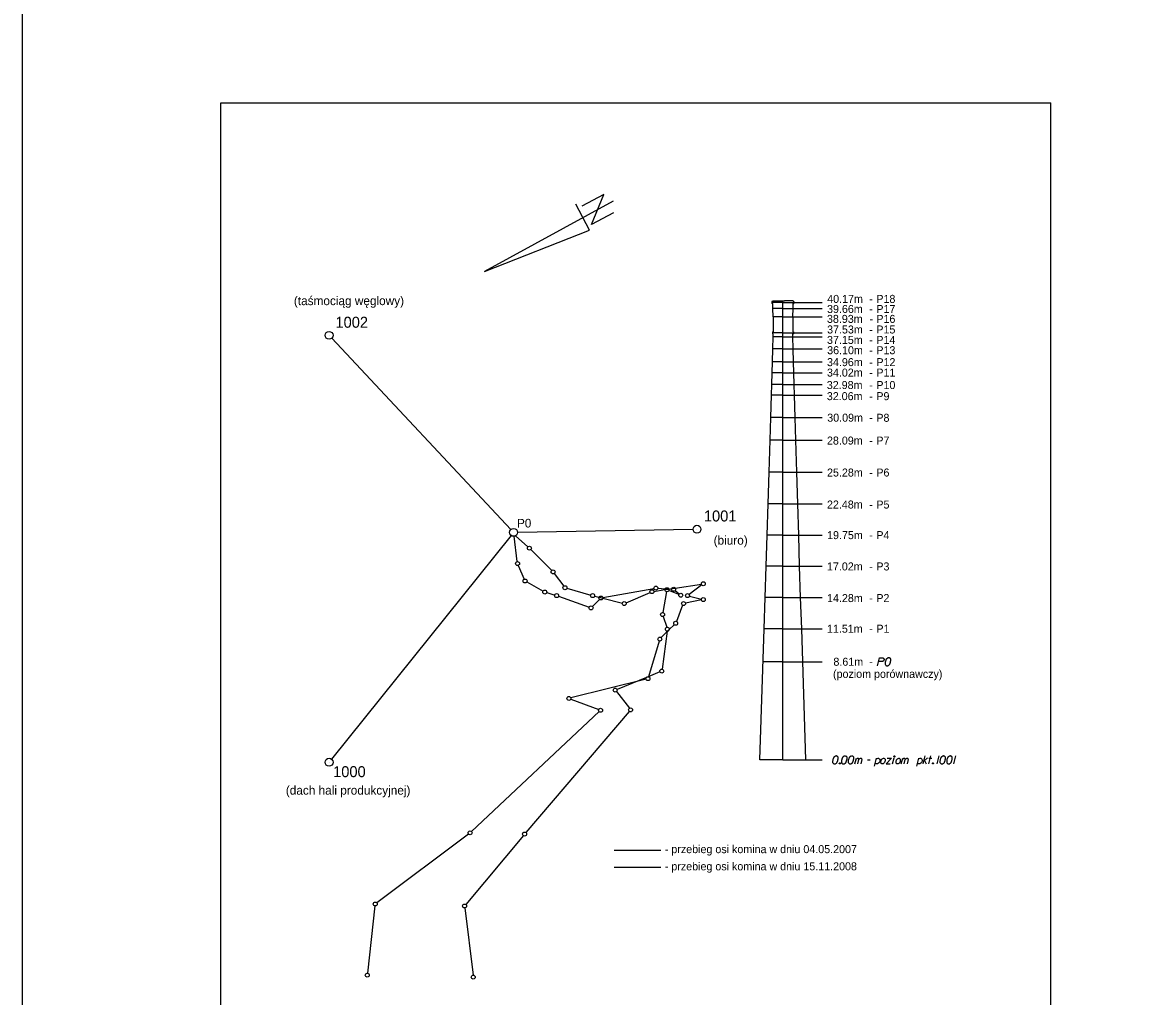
# Model space of a CAD drawing. Extents: x 138 to 6653, y -177 to 1520.
# Drawn here: x 287.42 to 316.02, y -56.31 to -31.68 of the extents above; entities that cross this region are included whole.
import ezdxf

# ---------------------------------------------------------------- set-up
doc = ezdxf.new("R2010")
doc.units = 0
for name, color, linetype in [('15 listopad 2008', 7, 'Continuous'), ('Opisy', 7, 'Continuous'), ('Ramka do drukowania', 7, 'Continuous'), ('Standart wykresów', 7, 'Continuous'), ('Wykresy 15 listopad 2008', 7, 'Continuous'), ('Wykresy 4 maj 2008', 7, 'Continuous')]:
    doc.layers.add(name, color=color, linetype=linetype)

msp = doc.modelspace()

# ---------------------------------------------------------------- linework, layer by layer
at = {"layer": '15 listopad 2008'}
for p, q in [((302.385, -52.613), (303.566, -52.613)), ((302.385, -53.045), (303.566, -53.045))]:
    msp.add_line(p, q, dxfattribs=at)
msp.add_lwpolyline([(287.418, 38.661), (413.872, 38.661), (413.872, -75.347), (287.418, -75.347)], close=True, dxfattribs=at)
at = {"layer": 'Opisy'}
for p, q in [((306.373, -38.741), (306.373, -38.765)), ((306.394, -38.741), (306.373, -38.741)), ((306.652, -38.765), (306.373, -38.765)), ((306.373, -38.765), (306.373, -38.79)), ((306.394, -38.79), (306.373, -38.79)), ((306.394, -38.717), (306.394, -38.741)), ((306.394, -38.717), (306.692, -38.717)), ((306.394, -38.913), (306.394, -38.79)), ((306.652, -50.331), (306.652, -38.717)), ((306.652, -38.765), (307.641, -38.765)), ((306.91, -38.717), (306.692, -38.717)), ((306.91, -38.717), (306.91, -38.741)), ((306.91, -38.741), (306.931, -38.741)), ((306.91, -38.79), (306.931, -38.79)), ((306.91, -38.913), (306.91, -38.79)), ((306.931, -38.741), (306.931, -38.765)), ((306.931, -38.765), (306.931, -38.79)), ((306.652, -38.913), (306.394, -38.913)), ((306.403, -39.123), (306.394, -38.913)), ((306.652, -39.123), (306.403, -39.123)), ((306.403, -39.123), (306.403, -39.501)), ((306.652, -38.913), (307.641, -38.913)), ((306.652, -39.123), (307.641, -39.123)), ((306.901, -39.123), (306.91, -38.913)), ((306.901, -39.123), (306.901, -39.501)), ((306.386, -39.501), (306.386, -39.527)), ((306.386, -39.501), (306.403, -39.501)), ((306.652, -39.527), (306.386, -39.527)), ((306.386, -39.527), (306.386, -39.552)), ((306.405, -39.552), (306.386, -39.552)), ((306.394, -39.939), (306.403, -39.635)), ((306.403, -39.635), (306.405, -39.552)), ((306.652, -39.635), (306.403, -39.635)), ((306.652, -39.527), (307.641, -39.527)), ((306.652, -39.635), (307.641, -39.635)), ((306.901, -39.635), (306.899, -39.552)), ((306.899, -39.552), (306.918, -39.552)), ((306.918, -39.501), (306.901, -39.501)), ((306.91, -39.939), (306.901, -39.635)), ((306.918, -39.501), (306.918, -39.527)), ((306.918, -39.527), (306.918, -39.552)), ((306.386, -40.268), (306.394, -39.939)), ((306.652, -39.939), (306.394, -39.939)), ((306.652, -39.939), (307.641, -39.939)), ((306.918, -40.268), (306.91, -39.939)), ((306.377, -40.538), (306.386, -40.268)), ((306.652, -40.268), (306.386, -40.268)), ((306.652, -40.268), (307.641, -40.268)), ((306.927, -40.538), (306.918, -40.268)), ((306.37, -40.837), (306.377, -40.538)), ((306.652, -40.538), (306.377, -40.538)), ((306.652, -40.538), (307.641, -40.538)), ((306.934, -40.837), (306.927, -40.538)), ((306.36, -41.103), (306.37, -40.837)), ((306.652, -40.837), (306.37, -40.837)), ((306.652, -40.837), (307.641, -40.837)), ((306.944, -41.103), (306.934, -40.837)), ((306.344, -41.67), (306.36, -41.103)), ((306.652, -41.103), (306.36, -41.103)), ((306.652, -41.103), (307.641, -41.103)), ((306.96, -41.67), (306.944, -41.103)), ((306.327, -42.244), (306.344, -41.67)), ((306.652, -41.67), (306.344, -41.67)), ((306.652, -41.67), (307.641, -41.67)), ((306.977, -42.244), (306.96, -41.67)), ((306.304, -43.055), (306.327, -42.244)), ((306.652, -42.244), (306.327, -42.244)), ((306.652, -42.244), (307.641, -42.244)), ((307, -43.055), (306.977, -42.244)), ((306.278, -43.859), (306.304, -43.055)), ((306.652, -43.055), (306.304, -43.055)), ((306.652, -43.055), (307.641, -43.055)), ((307.026, -43.859), (307, -43.055)), ((306.253, -44.645), (306.278, -43.859)), ((306.652, -43.859), (306.278, -43.859)), ((306.652, -43.859), (307.641, -43.859)), ((307.051, -44.645), (307.026, -43.859)), ((306.229, -45.431), (306.253, -44.645)), ((306.652, -44.645), (306.253, -44.645)), ((306.652, -44.645), (307.641, -44.645)), ((307.075, -45.431), (307.051, -44.645)), ((306.204, -46.221), (306.229, -45.431)), ((306.652, -45.431), (306.229, -45.431)), ((306.652, -45.431), (307.641, -45.431)), ((307.1, -46.221), (307.075, -45.431)), ((306.178, -47.017), (306.204, -46.221)), ((306.652, -46.221), (306.204, -46.221)), ((306.652, -46.221), (307.641, -46.221)), ((307.126, -47.017), (307.1, -46.221)), ((306.07, -50.331), (306.178, -47.017)), ((306.652, -47.017), (306.178, -47.017)), ((306.652, -47.017), (307.641, -47.017)), ((307.234, -50.331), (307.126, -47.017)), ((306.652, -47.853), (306.151, -47.853)), ((306.652, -47.853), (307.641, -47.853)), ((306.652, -50.331), (306.07, -50.331)), ((306.652, -50.331), (307.641, -50.331))]:
    msp.add_line(p, q, dxfattribs=at)
for points in [[(309.044, -47.951), (309.099, -47.749), (309.167, -47.749), (309.177, -47.75), (309.181, -47.752), (309.191, -47.756), (309.197, -47.761), (309.202, -47.768), (309.207, -47.776), (309.21, -47.787), (309.212, -47.796), (309.21, -47.804), (309.208, -47.811), (309.205, -47.817), (309.202, -47.822), (309.197, -47.828), (309.191, -47.833), (309.186, -47.836), (309.178, -47.839), (309.17, -47.841), (309.075, -47.841)], [(309.334, -47.749), (309.331, -47.749), (309.322, -47.75), (309.315, -47.752), (309.31, -47.753), (309.303, -47.756), (309.293, -47.761), (309.285, -47.766), (309.277, -47.772), (309.272, -47.779), (309.267, -47.787), (309.263, -47.795), (309.258, -47.804), (309.255, -47.811), (309.252, -47.82), (309.247, -47.836), (309.242, -47.86), (309.239, -47.879), (309.239, -47.897), (309.24, -47.909), (309.247, -47.924), (309.252, -47.932), (309.259, -47.941), (309.269, -47.948), (309.274, -47.949), (309.283, -47.951), (309.291, -47.951), (309.304, -47.949), (309.315, -47.946), (309.323, -47.941), (309.334, -47.933), (309.339, -47.929), (309.346, -47.922), (309.35, -47.916), (309.353, -47.911), (309.357, -47.903), (309.358, -47.9), (309.361, -47.892), (309.365, -47.882), (309.368, -47.873), (309.369, -47.866), (309.371, -47.862), (309.373, -47.855), (309.376, -47.841), (309.377, -47.833), (309.379, -47.825), (309.381, -47.814), (309.382, -47.799), (309.382, -47.795), (309.381, -47.788), (309.379, -47.782), (309.374, -47.772), (309.369, -47.766), (309.365, -47.761), (309.358, -47.756), (309.352, -47.753), (309.347, -47.752), (309.342, -47.75), (309.334, -47.749)], [(308.003, -50.233), (308, -50.233), (307.991, -50.235), (307.984, -50.236), (307.979, -50.238), (307.971, -50.241), (307.962, -50.246), (307.954, -50.251), (307.946, -50.257), (307.941, -50.263), (307.936, -50.271), (307.932, -50.279), (307.927, -50.289), (307.924, -50.295), (307.92, -50.305), (307.916, -50.321), (307.911, -50.345), (307.908, -50.364), (307.908, -50.381), (307.909, -50.394), (307.916, -50.408), (307.92, -50.416), (307.928, -50.426), (307.938, -50.432), (307.943, -50.434), (307.952, -50.435), (307.96, -50.435), (307.973, -50.434), (307.984, -50.431), (307.992, -50.426), (308.003, -50.418), (308.008, -50.413), (308.014, -50.407), (308.019, -50.4), (308.022, -50.396), (308.026, -50.388), (308.027, -50.384), (308.03, -50.376), (308.034, -50.367), (308.037, -50.357), (308.038, -50.351), (308.04, -50.346), (308.042, -50.34), (308.045, -50.325), (308.046, -50.318), (308.048, -50.31), (308.05, -50.298), (308.051, -50.284), (308.051, -50.279), (308.05, -50.273), (308.048, -50.267), (308.043, -50.257), (308.038, -50.251), (308.034, -50.246), (308.027, -50.241), (308.021, -50.238), (308.016, -50.236), (308.011, -50.235), (308.003, -50.233)], [(308.228, -50.233), (308.225, -50.233), (308.215, -50.235), (308.209, -50.236), (308.204, -50.238), (308.196, -50.241), (308.187, -50.246), (308.179, -50.251), (308.171, -50.257), (308.166, -50.263), (308.161, -50.271), (308.156, -50.279), (308.151, -50.289), (308.148, -50.295), (308.145, -50.305), (308.14, -50.321), (308.136, -50.345), (308.132, -50.364), (308.132, -50.381), (308.134, -50.394), (308.14, -50.408), (308.145, -50.416), (308.153, -50.426), (308.163, -50.432), (308.167, -50.434), (308.177, -50.435), (308.185, -50.435), (308.198, -50.434), (308.209, -50.431), (308.217, -50.426), (308.228, -50.418), (308.233, -50.413), (308.239, -50.407), (308.244, -50.4), (308.247, -50.396), (308.25, -50.388), (308.252, -50.384), (308.255, -50.376), (308.258, -50.367), (308.261, -50.357), (308.263, -50.351), (308.265, -50.346), (308.266, -50.34), (308.269, -50.325), (308.271, -50.318), (308.273, -50.31), (308.274, -50.298), (308.276, -50.284), (308.276, -50.279), (308.274, -50.273), (308.273, -50.267), (308.268, -50.257), (308.263, -50.251), (308.258, -50.246), (308.252, -50.241), (308.246, -50.238), (308.241, -50.236), (308.236, -50.235), (308.228, -50.233)], [(308.398, -50.233), (308.395, -50.233), (308.386, -50.235), (308.379, -50.236), (308.375, -50.238), (308.367, -50.241), (308.357, -50.246), (308.349, -50.251), (308.341, -50.257), (308.336, -50.263), (308.332, -50.271), (308.327, -50.279), (308.322, -50.289), (308.319, -50.295), (308.316, -50.305), (308.311, -50.321), (308.306, -50.345), (308.303, -50.364), (308.303, -50.381), (308.304, -50.394), (308.311, -50.408), (308.316, -50.416), (308.324, -50.426), (308.333, -50.432), (308.338, -50.434), (308.347, -50.435), (308.355, -50.435), (308.368, -50.434), (308.379, -50.431), (308.387, -50.426), (308.398, -50.418), (308.403, -50.413), (308.41, -50.407), (308.414, -50.4), (308.418, -50.396), (308.421, -50.388), (308.422, -50.384), (308.426, -50.376), (308.429, -50.367), (308.432, -50.357), (308.434, -50.351), (308.435, -50.346), (308.437, -50.34), (308.44, -50.325), (308.442, -50.318), (308.443, -50.31), (308.445, -50.298), (308.446, -50.284), (308.446, -50.279), (308.445, -50.273), (308.443, -50.267), (308.438, -50.257), (308.434, -50.251), (308.429, -50.246), (308.422, -50.241), (308.416, -50.238), (308.411, -50.236), (308.406, -50.235), (308.398, -50.233)], [(308.473, -50.435), (308.51, -50.29)], [(308.5, -50.329), (308.508, -50.311), (308.516, -50.302), (308.526, -50.295), (308.536, -50.29), (308.542, -50.287), (308.551, -50.287), (308.555, -50.289), (308.561, -50.295), (308.567, -50.303), (308.572, -50.318), (308.574, -50.325), (308.582, -50.311), (308.591, -50.302), (308.601, -50.295), (308.61, -50.29), (308.618, -50.287), (308.626, -50.287), (308.633, -50.289), (308.638, -50.295), (308.642, -50.303), (308.647, -50.318), (308.649, -50.325), (308.622, -50.435)], [(308.547, -50.435), (308.574, -50.325)], [(308.792, -50.333), (308.861, -50.333)], [(308.969, -50.488), (309.023, -50.289)], [(309.019, -50.306), (309.035, -50.294), (309.058, -50.289), (309.078, -50.292), (309.09, -50.302), (309.1, -50.314), (309.106, -50.332), (309.108, -50.348), (309.105, -50.362), (309.1, -50.38), (309.087, -50.399), (309.071, -50.416), (309.047, -50.432), (309.027, -50.435), (309.007, -50.434), (308.987, -50.423)], [(309.197, -50.289), (309.208, -50.289), (309.221, -50.295), (309.234, -50.313), (309.235, -50.321), (309.237, -50.329), (309.237, -50.335), (309.237, -50.359), (309.232, -50.375), (309.224, -50.394), (309.215, -50.41), (309.199, -50.424), (309.184, -50.435), (309.16, -50.435), (309.151, -50.432), (309.141, -50.424), (309.137, -50.416), (309.13, -50.397), (309.13, -50.369), (309.133, -50.359), (309.14, -50.338), (309.146, -50.327), (309.149, -50.321), (309.165, -50.303), (309.181, -50.294), (309.197, -50.289)], [(309.293, -50.286), (309.396, -50.286), (309.264, -50.435), (309.366, -50.435)], [(309.423, -50.435), (309.465, -50.281)], [(309.468, -50.233), (309.476, -50.233), (309.481, -50.236), (309.486, -50.243), (309.486, -50.251), (309.481, -50.257), (309.476, -50.26), (309.468, -50.26), (309.463, -50.257), (309.458, -50.251), (309.458, -50.243), (309.463, -50.236), (309.468, -50.233)], [(309.58, -50.289), (309.591, -50.289), (309.603, -50.295), (309.616, -50.313), (309.618, -50.321), (309.619, -50.329), (309.619, -50.335), (309.619, -50.359), (309.615, -50.375), (309.607, -50.394), (309.597, -50.41), (309.581, -50.424), (309.567, -50.435), (309.543, -50.435), (309.533, -50.432), (309.524, -50.424), (309.519, -50.416), (309.513, -50.397), (309.513, -50.369), (309.516, -50.359), (309.522, -50.338), (309.529, -50.327), (309.532, -50.321), (309.548, -50.303), (309.564, -50.294), (309.58, -50.289)], [(309.646, -50.435), (309.683, -50.29)], [(309.674, -50.329), (309.682, -50.311), (309.69, -50.302), (309.699, -50.295), (309.709, -50.29), (309.715, -50.287), (309.725, -50.287), (309.728, -50.289), (309.734, -50.295), (309.74, -50.303), (309.745, -50.318), (309.747, -50.325), (309.755, -50.311), (309.764, -50.302), (309.774, -50.295), (309.784, -50.29), (309.791, -50.287), (309.799, -50.287), (309.806, -50.289), (309.811, -50.295), (309.815, -50.303), (309.82, -50.318), (309.822, -50.325), (309.795, -50.435)], [(309.72, -50.435), (309.747, -50.325)], [(310.037, -50.488), (310.091, -50.289)], [(310.086, -50.306), (310.102, -50.294), (310.126, -50.289), (310.145, -50.292), (310.158, -50.302), (310.168, -50.314), (310.174, -50.332), (310.176, -50.348), (310.172, -50.362), (310.168, -50.38), (310.155, -50.399), (310.139, -50.416), (310.115, -50.432), (310.094, -50.435), (310.075, -50.434), (310.054, -50.423)], [(310.198, -50.435), (310.252, -50.233)], [(310.217, -50.364), (310.313, -50.284)], [(310.34, -50.435), (310.392, -50.233)], [(310.34, -50.289), (310.416, -50.289)], [(310.596, -50.233), (310.542, -50.435)], [(310.719, -50.233), (310.716, -50.233), (310.706, -50.235), (310.7, -50.236), (310.695, -50.238), (310.687, -50.241), (310.678, -50.246), (310.67, -50.251), (310.662, -50.257), (310.657, -50.263), (310.652, -50.271), (310.647, -50.279), (310.642, -50.289), (310.639, -50.295), (310.636, -50.305), (310.631, -50.321), (310.627, -50.345), (310.623, -50.364), (310.623, -50.381), (310.625, -50.394), (310.631, -50.408), (310.636, -50.416), (310.644, -50.426), (310.654, -50.432), (310.658, -50.434), (310.668, -50.435), (310.676, -50.435), (310.689, -50.434), (310.7, -50.431), (310.708, -50.426), (310.719, -50.418), (310.724, -50.413), (310.73, -50.407), (310.735, -50.4), (310.738, -50.396), (310.741, -50.388), (310.743, -50.384), (310.746, -50.376), (310.749, -50.367), (310.752, -50.357), (310.754, -50.351), (310.756, -50.346), (310.757, -50.34), (310.76, -50.325), (310.762, -50.318), (310.764, -50.31), (310.765, -50.298), (310.767, -50.284), (310.767, -50.279), (310.765, -50.273), (310.764, -50.267), (310.759, -50.257), (310.754, -50.251), (310.749, -50.246), (310.743, -50.241), (310.736, -50.238), (310.732, -50.236), (310.727, -50.235), (310.719, -50.233)], [(310.889, -50.233), (310.886, -50.233), (310.877, -50.235), (310.87, -50.236), (310.866, -50.238), (310.858, -50.241), (310.848, -50.246), (310.84, -50.251), (310.832, -50.257), (310.827, -50.263), (310.823, -50.271), (310.818, -50.279), (310.813, -50.289), (310.81, -50.295), (310.807, -50.305), (310.802, -50.321), (310.797, -50.345), (310.794, -50.364), (310.794, -50.381), (310.795, -50.394), (310.802, -50.408), (310.807, -50.416), (310.815, -50.426), (310.824, -50.432), (310.829, -50.434), (310.838, -50.435), (310.846, -50.435), (310.859, -50.434), (310.87, -50.431), (310.878, -50.426), (310.889, -50.418), (310.894, -50.413), (310.901, -50.407), (310.905, -50.4), (310.909, -50.396), (310.912, -50.388), (310.913, -50.384), (310.917, -50.376), (310.92, -50.367), (310.923, -50.357), (310.925, -50.351), (310.926, -50.346), (310.928, -50.34), (310.931, -50.325), (310.932, -50.318), (310.934, -50.31), (310.936, -50.298), (310.937, -50.284), (310.937, -50.279), (310.936, -50.273), (310.934, -50.267), (310.929, -50.257), (310.925, -50.251), (310.92, -50.246), (310.913, -50.241), (310.907, -50.238), (310.902, -50.236), (310.897, -50.235), (310.889, -50.233)], [(311.019, -50.233), (310.964, -50.435)], [(308.088, -50.408), (308.096, -50.408), (308.1, -50.412), (308.105, -50.418), (308.105, -50.426), (308.1, -50.432), (308.096, -50.435), (308.088, -50.435), (308.083, -50.432), (308.078, -50.426), (308.078, -50.418), (308.083, -50.412), (308.088, -50.408)], [(310.236, -50.348), (310.278, -50.435)], [(310.443, -50.408), (310.451, -50.408), (310.456, -50.412), (310.461, -50.418), (310.461, -50.426), (310.456, -50.432), (310.451, -50.435), (310.443, -50.435), (310.438, -50.432), (310.434, -50.426), (310.434, -50.418), (310.438, -50.412), (310.443, -50.408)]]:
    msp.add_lwpolyline(points, dxfattribs=at)
at = {"layer": 'Ramka do drukowania'}
for p, q in [((292.431, -63.414), (292.431, -33.714)), ((292.431, -33.714), (313.431, -33.714)), ((313.431, -63.414), (313.431, -33.714))]:
    msp.add_line(p, q, dxfattribs=at)
at = {"layer": 'Standart wykresów'}
for p, q in [((302.121, -36.028), (301.564, -36.324)), ((301.81, -36.788), (302.121, -36.028)), ((302.36, -36.196), (299.104, -37.977)), ((301.759, -36.932), (301.412, -36.274)), ((302.367, -36.491), (301.81, -36.788)), ((299.104, -37.977), (301.759, -36.932)), ((295.171, -39.593), (295.171, -39.593)), ((299.77, -44.504), (295.239, -39.666)), ((299.938, -44.575), (304.378, -44.5)), ((304.478, -44.498), (304.478, -44.498)), ((299.776, -44.655), (295.234, -50.313)), ((295.171, -50.391), (295.171, -50.391))]:
    msp.add_line(p, q, dxfattribs=at)
for centre in [(295.171, -39.593), (304.478, -44.498), (295.171, -50.391)]:
    msp.add_circle(centre, 0.1, dxfattribs=at)
at = {"layer": 'Wykresy 15 listopad 2008'}
for p, q in [((299.932, -45.317), (299.851, -44.676)), ((299.958, -45.413), (300.109, -45.761)), ((300.172, -45.831), (300.585, -46.062)), ((302.098, -46.228), (303.389, -45.996)), ((303.488, -45.99), (303.675, -46.003)), ((303.675, -46.003), (303.765, -46.009)), ((303.765, -46.009), (303.839, -46.013)), ((304.022, -46.148), (303.765, -46.045)), ((303.927, -46.049), (304.03, -46.135)), ((300.676, -46.101), (300.881, -46.162)), ((300.976, -46.194), (301.751, -46.47)), ((301.834, -46.451), (302.013, -46.272)), ((303.71, -46.076), (303.617, -46.607)), ((303.624, -46.704), (303.713, -46.979)), ((303.722, -47.076), (303.595, -48.037)), ((303.2, -48.245), (302.455, -48.548)), ((303.244, -48.227), (303.2, -48.245)), ((303.542, -48.106), (303.244, -48.227)), ((302.439, -48.606), (302.768, -49.027)), ((302.766, -49.105), (300.151, -52.169)), ((300.086, -52.245), (298.63, -53.988)), ((298.604, -54.076), (298.812, -55.777))]:
    msp.add_line(p, q, dxfattribs=at)
for centre, radius in [((299.838, -44.577), 0.1), ((299.938, -45.367), 0.05), ((300.128, -45.807), 0.05), ((300.628, -46.087), 0.05), ((303.438, -45.987), 0.05), ((303.718, -46.027), 0.05), ((303.888, -46.017), 0.05), ((300.928, -46.177), 0.05), ((302.048, -46.237), 0.05), ((304.068, -46.167), 0.05), ((301.798, -46.487), 0.05), ((303.608, -46.657), 0.05), ((303.728, -47.027), 0.05), ((303.588, -48.087), 0.05), ((302.408, -48.567), 0.05), ((302.798, -49.067), 0.05), ((300.118, -52.207), 0.05), ((298.598, -54.027), 0.05), ((298.818, -55.827), 0.05)]:
    msp.add_circle(centre, radius, dxfattribs=at)
at = {"layer": 'Wykresy 4 maj 2008'}
for p, q in [((299.89, -44.663), (300.203, -44.941)), ((300.274, -45.012), (300.803, -45.541)), ((300.868, -45.617), (301.108, -45.937)), ((301.186, -45.99), (301.79, -46.163)), ((303.388, -46.069), (303.668, -46.026)), ((303.668, -46.026), (303.766, -46.011)), ((303.766, -46.011), (303.842, -45.999)), ((303.842, -45.999), (303.928, -45.986)), ((303.928, -45.986), (304.589, -45.884)), ((304.598, -45.907), (304.278, -46.147)), ((301.887, -46.189), (302.002, -46.218)), ((302.002, -46.218), (302.098, -46.242)), ((302.098, -46.242), (302.59, -46.365)), ((302.684, -46.357), (303.292, -46.096)), ((304.589, -46.286), (304.187, -46.365)), ((304.286, -46.193), (304.59, -46.265)), ((304.113, -46.42), (303.956, -46.83)), ((303.903, -46.912), (303.778, -47.033)), ((303.733, -47.077), (303.568, -47.237)), ((303.778, -47.033), (303.733, -47.077)), ((303.525, -47.325), (303.253, -48.229)), ((303.19, -48.289), (301.287, -48.765)), ((301.285, -48.794), (301.992, -49.059)), ((302.002, -49.111), (298.775, -52.143)), ((298.698, -52.207), (296.378, -53.946)), ((296.33, -54.026), (296.144, -55.727))]:
    msp.add_line(p, q, dxfattribs=at)
for centre, radius in [((299.838, -44.577), 0.1), ((300.238, -44.977), 0.05), ((300.838, -45.577), 0.05), ((301.138, -45.977), 0.05), ((303.338, -46.077), 0.05), ((304.638, -45.877), 0.05), ((301.838, -46.177), 0.05), ((302.638, -46.377), 0.05), ((304.138, -46.377), 0.05), ((304.238, -46.177), 0.05), ((304.638, -46.277), 0.05), ((303.938, -46.877), 0.05), ((303.538, -47.277), 0.05), ((303.238, -48.277), 0.05), ((301.238, -48.777), 0.05), ((302.038, -49.077), 0.05), ((298.738, -52.177), 0.05), ((296.338, -53.977), 0.05), ((296.138, -55.777), 0.05)]:
    msp.add_circle(centre, radius, dxfattribs=at)

# ---------------------------------------------------------------- texts
at = {"layer": 'Opisy'}
for s, height, p in [('40.17m', 0.2024, (307.772, -38.773)), ('P18', 0.2024, (309.015, -38.773)), ('39.66m', 0.2024, (307.768, -39.028)), ('-', 0.202, (308.835, -38.773)), ('P17', 0.2024, (309.015, -39.028)), ('38.93m', 0.2024, (307.766, -39.279)), ('-', 0.202, (308.837, -39.028)), ('P16', 0.2024, (309.015, -39.279)), ('37.53m', 0.2024, (307.769, -39.547)), ('-', 0.202, (308.835, -39.547)), ('-', 0.202, (308.841, -39.279)), ('P15', 0.2024, (309.015, -39.547)), ('37.15m', 0.2024, (307.767, -39.811)), ('-', 0.202, (308.835, -39.811)), ('P14', 0.2024, (309.015, -39.811)), ('36.10m', 0.2024, (307.771, -40.071)), ('-', 0.202, (308.837, -40.071)), ('P13', 0.2024, (309.015, -40.071)), ('34.96m', 0.2024, (307.767, -40.373)), ('-', 0.202, (308.837, -40.373)), ('P12', 0.2024, (309.016, -40.373)), ('34.02m', 0.2024, (307.766, -40.637)), ('-', 0.202, (308.837, -40.637)), ('P11', 0.2024, (309.015, -40.637)), ('32.98m', 0.2024, (307.762, -40.952)), ('-', 0.202, (308.837, -40.952)), ('P10', 0.2024, (309.015, -40.952)), ('32.06m', 0.2024, (307.762, -41.233)), ('-', 0.202, (308.837, -41.233)), ('P9', 0.2024, (309.015, -41.233)), ('30.09m', 0.2024, (307.773, -41.778)), ('-', 0.202, (308.837, -41.778)), ('P8', 0.2024, (309.015, -41.78)), ('28.09m', 0.2024, (307.766, -42.356)), ('-', 0.202, (308.837, -42.356)), ('P7', 0.2024, (309.015, -42.356)), ('25.28m', 0.2024, (307.768, -43.165)), ('-', 0.202, (308.835, -43.165)), ('P6', 0.2024, (309.015, -43.165)), ('22.48m', 0.2024, (307.766, -43.974)), ('-', 0.202, (308.835, -43.974)), ('P5', 0.2024, (309.015, -43.974)), ('19.75m', 0.2024, (307.769, -44.748)), ('P4', 0.2024, (309.015, -44.748)), ('-', 0.202, (308.835, -44.748)), ('17.02m', 0.2024, (307.766, -45.54)), ('-', 0.202, (308.835, -45.54)), ('P3', 0.2024, (309.015, -45.54)), ('14.28m', 0.2024, (307.768, -46.34)), ('-', 0.202, (308.836, -46.34)), ('P2', 0.2024, (309.015, -46.34)), ('11.51m', 0.2024, (307.766, -47.115)), ('-', 0.202, (308.835, -47.115)), ('P1', 0.2024, (309.016, -47.115)), ('8.61m', 0.2024, (307.929, -47.951)), ('(poziom porównawczy)', 0.2024, (307.919, -48.258)), ('-', 0.202, (308.835, -47.951)), ('- przebieg osi komina w dniu 04.05.2007', 0.2024, (303.664, -52.691)), ('- przebieg osi komina w dniu 15.11.2008', 0.2024, (303.664, -53.125))]:
    msp.add_text(s, height=height, dxfattribs=at).set_placement(p)
at = {"layer": 'Standart wykresów'}
for s, height, p in [('(taśmociąg węglowy)', 0.22315, (294.281, -38.83)), ('1002', 0.2771, (295.332, -39.401)), ('1001', 0.2771, (304.652, -44.301)), ('(biuro)', 0.2231, (304.899, -44.887)), ('1000', 0.2771, (295.273, -50.768)), ('(dach hali produkcyjnej)', 0.22315, (294.077, -51.211))]:
    msp.add_text(s, height=height, dxfattribs=at).set_placement(p)
at = {"layer": 'Wykresy 4 maj 2008'}
msp.add_text('P0', height=0.22, dxfattribs=at).set_placement((299.927, -44.455))

doc.saveas('drawing.dxf')
